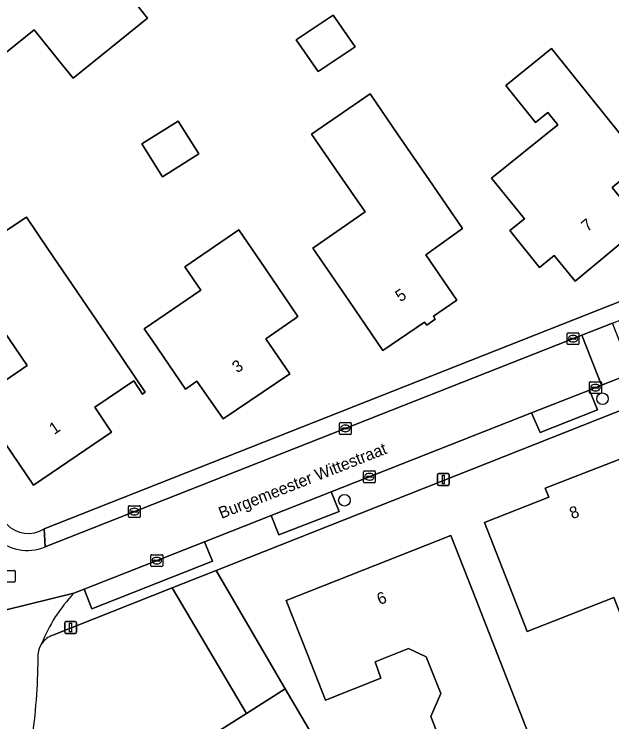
# Model space of a CAD drawing. Extents: x 159499 to 160349, y 382524 to 383273.
# Drawn here: x 159802.6 to 159853.2, y 382906.1 to 382966 of the extents above; entities that cross this region are included whole.
import ezdxf

# ---------------------------------------------------------------- set-up
doc = ezdxf.new("R2010")
doc.units = 0
for name, color, linetype in [('IMGEO_Boom', 7, 'Continuous'), ('IMGEO_Erf', 7, 'Continuous'), ('IMGEO_Groenvoorziening', 7, 'Continuous'), ('IMGEO_Kolk', 7, 'Continuous'), ('IMGEO_Lichtmast', 7, 'Continuous'), ('IMGEO_Openbare_ruimte_label', 7, 'Continuous'), ('IMGEO_Pand', 7, 'Continuous'), ('IMGEO_Pand_nummerreeks', 7, 'Continuous'), ('IMGEO_Parkeervlak_open', 7, 'Continuous'), ('IMGEO_Rijbaan_lokaal_open', 7, 'Continuous'), ('IMGEO_Rioolput', 7, 'Continuous'), ('IMGEO_Voetpad_open', 7, 'Continuous')]:
    doc.layers.add(name, color=color, linetype=linetype)

msp = doc.modelspace()

# ---------------------------------------------------------------- linework, layer by layer
at = {"layer": 'IMGEO_Boom'}
for centre in [(159852.44, 382933.464), (159830.58, 382924.866)]:
    msp.add_circle(centre, 0.489, dxfattribs=at)
at = {"layer": 'IMGEO_Erf'}
for points in [[(159810.687, 382969.677), (159812.684, 382967.19), (159813.906, 382965.668), (159807.597, 382960.604), (159806.377, 382962.124), (159804.314, 382964.694), (159800.336, 382961.498), (159797.462, 382965.076), (159794.331, 382968.974), (159800.665, 382974.051), (159803.594, 382970.401), (159807.555, 382973.575)], [(159829.625, 382965.936), (159831.488, 382963.248), (159828.357, 382961.164), (159826.494, 382963.852)], [(159848.109, 382963.101), (159852.721, 382957.378), (159855.859, 382953.485), (159853.267, 382951.341), (159855.83, 382948.153), (159850.122, 382943.417), (159848.351, 382945.581), (159847.105, 382944.572), (159844.579, 382947.699), (159845.829, 382948.687), (159843.044, 382952.124), (159848.642, 382956.635), (159847.801, 382957.68), (159846.764, 382956.845), (159844.238, 382959.981)], [(159832.762, 382959.268), (159835.116, 382955.835), (159837.748, 382951.997), (159840.576, 382947.873), (159837.474, 382945.651), (159840.098, 382941.809), (159838.121, 382940.456), (159838.275, 382940.209), (159837.549, 382939.692), (159837.359, 382939.953), (159833.819, 382937.55), (159831, 382941.681), (159827.903, 382946.22), (159832.335, 382949.291), (159830.175, 382952.411), (159827.804, 382955.868)], [(159816.49, 382956.966), (159818.245, 382954.196), (159815.182, 382952.255), (159813.426, 382955.025)], [(159807.09, 382943.762), (159810.9, 382938.157), (159813.711, 382934.022), (159813.481, 382933.854), (159812.732, 382934.98), (159809.429, 382932.761), (159810.232, 382931.566), (159810.856, 382930.637), (159804.242, 382926.147), (159799.36, 382933.326), (159803.7, 382936.281), (159799.681, 382942.183), (159797.796, 382944.952), (159803.648, 382948.828), (159805.528, 382946.062)], [(159826.646, 382940.418), (159826.404, 382940.241), (159823.924, 382938.546), (159825.958, 382935.584), (159820.316, 382931.756), (159818.093, 382934.961), (159817.109, 382934.282), (159814.294, 382938.414), (159813.628, 382939.392), (159818.417, 382942.652), (159817.066, 382944.633), (159821.648, 382947.753), (159823.831, 382944.55)], [(159860.258, 382915.772), (159854.598, 382913.555), (159853.389, 382916.644), (159846.046, 382913.769), (159842.432, 382922.996), (159847.888, 382925.132), (159847.59, 382925.89), (159855.15, 382928.82)], [(159846.866, 382903.296), (159840.225, 382900.649), (159837.9, 382906.568), (159838.747, 382908.507), (159837.494, 382911.622), (159836, 382912.309), (159833.186, 382911.18), (159833.664, 382909.806), (159828.984, 382907.938), (159827.481, 382911.745), (159825.644, 382916.395), (159839.605, 382921.884), (159841.424, 382917.227)]]:
    msp.add_lwpolyline(points, close=True, dxfattribs=at)
for points in [[(159805.148, 382922.46), (159871.857, 382948.784)], [(159876.5, 382941.374), (159819.719, 382918.916), (159824.775, 382910.258), (159825.57, 382908.897), (159828.09, 382904.582), (159835.486, 382892.537), (159864.819, 382904.203), (159872.995, 382898.326), (159887.39, 382888.81), (159898.82, 382899.272), (159898.169, 382899.97), (159898.75, 382900.538), (159897.338, 382901.983), (159899.452, 382904.048), (159897.237, 382906.374), (159896.798, 382905.952), (159895.793, 382906.945), (159896.237, 382907.385), (159892.868, 382910.834), (159884.436, 382902.771), (159882.298, 382900.727), (159879.16, 382904.008), (159881.283, 382906.041), (159891.329, 382915.663)]]:
    msp.add_lwpolyline(points, dxfattribs=at)
msp.add_arc((159803.794, 382924.566), 2.504, 222.61592, 302.72825, dxfattribs=at)
at = {"layer": 'IMGEO_Groenvoorziening'}
msp.add_lwpolyline([(159825.57, 382908.897), (159824.775, 382910.258), (159819.719, 382918.916), (159816, 382917.445), (159822.273, 382906.815)], close=True, dxfattribs=at)
for points in [[(159818.914, 382904.693), (159822.273, 382906.815), (159816, 382917.445), (159805.876, 382913.439)], [(159828.09, 382904.582), (159825.57, 382908.897), (159822.273, 382906.815), (159818.914, 382904.693)]]:
    msp.add_lwpolyline(points, dxfattribs=at)
for centre, radius, start, end in [((159806.442, 382911.721), 1.809, 108.23379, 146.35942), ((159806.437, 382911.725), 1.802, 146.3718, 174.39122), ((159750.82, 382912.013), 53.823, 352.42978, 359.88104)]:
    msp.add_arc(centre, radius, start, end, dxfattribs=at)
at = {"layer": 'IMGEO_Kolk'}
for p, q in [((159849.443, 382938.12), (159849.443, 382938.972)), ((159849.518, 382939.046), (159850.37, 382939.046)), ((159850.444, 382938.972), (159850.444, 382938.12)), ((159849.702, 382938.54), (159849.702, 382938.552)), ((159850.14, 382938.503), (159849.742, 382938.503)), ((159849.745, 382938.589), (159850.143, 382938.589)), ((159849.931, 382938.826), (159849.956, 382938.826)), ((159850.186, 382938.552), (159850.186, 382938.54)), ((159850.37, 382938.046), (159849.518, 382938.046)), ((159849.954, 382938.266), (159849.929, 382938.266)), ((159851.337, 382933.975), (159851.337, 382934.827)), ((159851.412, 382934.901), (159852.264, 382934.901)), ((159852.338, 382934.827), (159852.338, 382933.975)), ((159851.596, 382934.395), (159851.596, 382934.407)), ((159852.034, 382934.358), (159851.636, 382934.358)), ((159851.639, 382934.444), (159852.037, 382934.444)), ((159851.825, 382934.681), (159851.85, 382934.681)), ((159852.08, 382934.407), (159852.08, 382934.395)), ((159852.264, 382933.901), (159851.412, 382933.901)), ((159851.848, 382934.121), (159851.823, 382934.121)), ((159830.163, 382930.523), (159830.163, 382931.375)), ((159830.238, 382931.449), (159831.09, 382931.449)), ((159830.651, 382931.229), (159830.676, 382931.229)), ((159831.164, 382931.375), (159831.164, 382930.523)), ((159830.422, 382930.943), (159830.422, 382930.955)), ((159830.86, 382930.906), (159830.462, 382930.906)), ((159830.465, 382930.992), (159830.863, 382930.992)), ((159830.674, 382930.669), (159830.649, 382930.669)), ((159830.906, 382930.955), (159830.906, 382930.943)), ((159831.09, 382930.449), (159830.238, 382930.449)), ((159832.191, 382926.429), (159832.191, 382927.281)), ((159832.266, 382927.355), (159833.118, 382927.355)), ((159832.679, 382927.135), (159832.704, 382927.135)), ((159833.192, 382927.281), (159833.192, 382926.429)), ((159832.45, 382926.849), (159832.45, 382926.861)), ((159832.888, 382926.812), (159832.49, 382926.812)), ((159832.493, 382926.898), (159832.891, 382926.898)), ((159832.702, 382926.575), (159832.677, 382926.575)), ((159832.934, 382926.861), (159832.934, 382926.849)), ((159833.118, 382926.355), (159832.266, 382926.355)), ((159812.291, 382923.481), (159812.291, 382924.333)), ((159812.366, 382924.407), (159813.218, 382924.407)), ((159812.779, 382924.187), (159812.804, 382924.187)), ((159813.292, 382924.333), (159813.292, 382923.481)), ((159813.218, 382923.407), (159812.366, 382923.407)), ((159812.55, 382923.901), (159812.55, 382923.913)), ((159812.988, 382923.864), (159812.59, 382923.864)), ((159812.593, 382923.95), (159812.991, 382923.95)), ((159812.802, 382923.627), (159812.777, 382923.627)), ((159813.034, 382923.913), (159813.034, 382923.901)), ((159814.186, 382919.332), (159814.186, 382920.184)), ((159814.261, 382920.258), (159815.113, 382920.258)), ((159814.674, 382920.038), (159814.699, 382920.038)), ((159815.187, 382920.184), (159815.187, 382919.332)), ((159815.113, 382919.258), (159814.261, 382919.258)), ((159814.445, 382919.752), (159814.445, 382919.764)), ((159814.883, 382919.715), (159814.485, 382919.715)), ((159814.488, 382919.801), (159814.886, 382919.801)), ((159814.697, 382919.478), (159814.672, 382919.478)), ((159814.929, 382919.764), (159814.929, 382919.752))]:
    msp.add_line(p, q, dxfattribs=at)
for points in [[(159849.443, 382938.12), (159849.443, 382938.972)], [(159849.518, 382939.046), (159850.37, 382939.046)], [(159850.444, 382938.972), (159850.444, 382938.12)], [(159850.37, 382938.046), (159849.518, 382938.046)], [(159851.337, 382933.975), (159851.337, 382934.827)], [(159851.412, 382934.901), (159852.264, 382934.901)], [(159852.338, 382934.827), (159852.338, 382933.975)], [(159852.264, 382933.901), (159851.412, 382933.901)], [(159830.163, 382930.523), (159830.163, 382931.375)], [(159830.238, 382931.449), (159831.09, 382931.449)], [(159831.164, 382931.375), (159831.164, 382930.523)], [(159831.09, 382930.449), (159830.238, 382930.449)], [(159832.191, 382926.429), (159832.191, 382927.281)], [(159832.266, 382927.355), (159833.118, 382927.355)], [(159833.192, 382927.281), (159833.192, 382926.429)], [(159833.118, 382926.355), (159832.266, 382926.355)], [(159812.291, 382923.481), (159812.291, 382924.333)], [(159812.366, 382924.407), (159813.218, 382924.407)], [(159813.292, 382924.333), (159813.292, 382923.481)], [(159813.218, 382923.407), (159812.366, 382923.407)], [(159814.186, 382919.332), (159814.186, 382920.184)], [(159814.261, 382920.258), (159815.113, 382920.258)], [(159815.187, 382920.184), (159815.187, 382919.332)], [(159815.113, 382919.258), (159814.261, 382919.258)]]:
    msp.add_lwpolyline(points, dxfattribs=at)
for centre, radius, start, end in [((159849.52, 382938.97), 0.0765, 91.55205, 178.44795), ((159849.52, 382938.97), 0.0765, 91.55205, 178.44795), ((159850.368, 382938.97), 0.0765, 1.55205, 88.44795), ((159850.368, 382938.97), 0.0765, 1.55205, 88.44795), ((159849.742, 382938.549), 0.0403, 85.87752, 175.75265), ((159849.739, 382938.539), 0.0366, 178.93798, 274.71019), ((159850.143, 382938.546), 0.043, 264.86636, 352.45326), ((159850.147, 382938.551), 0.0386, 1.73085, 96.63898), ((159849.52, 382938.122), 0.0765, 181.55205, 268.44795), ((159849.52, 382938.122), 0.0765, 181.55205, 268.44795), ((159850.368, 382938.122), 0.0765, 271.55205, 358.44795), ((159850.368, 382938.122), 0.0765, 271.55205, 358.44795), ((159851.414, 382934.825), 0.0765, 91.55205, 178.44795), ((159851.414, 382934.825), 0.0765, 91.55205, 178.44795), ((159852.262, 382934.825), 0.0765, 1.55205, 88.44795), ((159852.262, 382934.825), 0.0765, 1.55205, 88.44795), ((159851.636, 382934.404), 0.0403, 85.87752, 175.75265), ((159851.633, 382934.394), 0.0366, 178.93798, 274.71019), ((159852.037, 382934.401), 0.043, 264.86636, 352.45326), ((159852.041, 382934.406), 0.0386, 1.73085, 96.63898), ((159851.414, 382933.977), 0.0765, 181.55205, 268.44795), ((159851.414, 382933.977), 0.0765, 181.55205, 268.44795), ((159852.262, 382933.977), 0.0765, 271.55205, 358.44795), ((159852.262, 382933.977), 0.0765, 271.55205, 358.44795), ((159830.24, 382931.373), 0.0765, 91.55205, 178.44795), ((159830.24, 382931.373), 0.0765, 91.55205, 178.44795), ((159831.088, 382931.373), 0.0765, 1.55205, 88.44795), ((159831.088, 382931.373), 0.0765, 1.55205, 88.44795), ((159830.462, 382930.952), 0.0403, 85.87752, 175.75265), ((159830.459, 382930.942), 0.0366, 178.93798, 274.71019), ((159830.863, 382930.949), 0.043, 264.86636, 352.45326), ((159830.867, 382930.954), 0.0386, 1.73085, 96.63898), ((159830.24, 382930.525), 0.0765, 181.55205, 268.44795), ((159830.24, 382930.525), 0.0765, 181.55205, 268.44795), ((159831.088, 382930.525), 0.0765, 271.55205, 358.44795), ((159831.088, 382930.525), 0.0765, 271.55205, 358.44795), ((159832.268, 382927.279), 0.0765, 91.55205, 178.44795), ((159832.268, 382927.279), 0.0765, 91.55205, 178.44795), ((159833.116, 382927.279), 0.0765, 1.55205, 88.44795), ((159833.116, 382927.279), 0.0765, 1.55205, 88.44795), ((159832.268, 382926.431), 0.0765, 181.55205, 268.44795), ((159832.268, 382926.431), 0.0765, 181.55205, 268.44795), ((159832.49, 382926.858), 0.0403, 85.87752, 175.75265), ((159832.487, 382926.848), 0.0366, 178.93798, 274.71019), ((159832.891, 382926.855), 0.043, 264.86636, 352.45326), ((159832.895, 382926.86), 0.0386, 1.73085, 96.63898), ((159833.116, 382926.431), 0.0765, 271.55205, 358.44795), ((159833.116, 382926.431), 0.0765, 271.55205, 358.44795), ((159812.368, 382924.331), 0.0765, 91.55205, 178.44795), ((159812.368, 382924.331), 0.0765, 91.55205, 178.44795), ((159813.216, 382924.331), 0.0765, 1.55205, 88.44795), ((159813.216, 382924.331), 0.0765, 1.55205, 88.44795), ((159812.368, 382923.483), 0.0765, 181.55205, 268.44795), ((159812.368, 382923.483), 0.0765, 181.55205, 268.44795), ((159812.59, 382923.91), 0.0403, 85.87752, 175.75265), ((159812.587, 382923.9), 0.0366, 178.93798, 274.71019), ((159812.991, 382923.907), 0.043, 264.86636, 352.45326), ((159812.995, 382923.912), 0.0386, 1.73085, 96.63898), ((159813.216, 382923.483), 0.0765, 271.55205, 358.44795), ((159813.216, 382923.483), 0.0765, 271.55205, 358.44795), ((159814.263, 382920.182), 0.0765, 91.55205, 178.44795), ((159814.263, 382920.182), 0.0765, 91.55205, 178.44795), ((159815.111, 382920.182), 0.0765, 1.55205, 88.44795), ((159815.111, 382920.182), 0.0765, 1.55205, 88.44795), ((159814.263, 382919.334), 0.0765, 181.55205, 268.44795), ((159814.263, 382919.334), 0.0765, 181.55205, 268.44795), ((159814.485, 382919.761), 0.0403, 85.87752, 175.75265), ((159814.482, 382919.751), 0.0366, 178.93798, 274.71019), ((159814.886, 382919.758), 0.043, 264.86636, 352.45326), ((159814.89, 382919.763), 0.0386, 1.73085, 96.63898), ((159815.111, 382919.334), 0.0765, 271.55205, 358.44795), ((159815.111, 382919.334), 0.0765, 271.55205, 358.44795)]:
    msp.add_arc(centre, radius, start, end, dxfattribs=at)
for centre, major_axis, ratio, start_param, end_param in [((159849.93, 382938.546), (-0.387, 0.002), 0.722429, 4.712389, 7.853982), ((159849.955, 382938.546), (-0.39, 0.002), 0.717154, 1.570796, 4.712389), ((159851.824, 382934.401), (-0.387, 0.002), 0.722429, 4.712389, 7.853982), ((159851.849, 382934.401), (-0.39, 0.002), 0.717154, 1.570796, 4.712389), ((159830.65, 382930.949), (-0.387, 0.002), 0.722429, 4.712389, 7.853982), ((159830.675, 382930.949), (-0.39, 0.002), 0.717154, 1.570796, 4.712389), ((159832.678, 382926.855), (-0.387, 0.002), 0.722429, 4.712389, 7.853982), ((159832.703, 382926.855), (-0.39, 0.002), 0.717154, 1.570796, 4.712389), ((159812.778, 382923.907), (-0.387, 0.002), 0.722429, 4.712389, 7.853982), ((159812.803, 382923.907), (-0.39, 0.002), 0.717154, 1.570796, 4.712389), ((159814.673, 382919.758), (-0.387, 0.002), 0.722429, 4.712389, 7.853982), ((159814.698, 382919.758), (-0.39, 0.002), 0.717154, 1.570796, 4.712389)]:
    msp.add_ellipse(centre, major_axis=major_axis, ratio=ratio, start_param=start_param, end_param=end_param, dxfattribs=at)
at = {"layer": 'IMGEO_Lichtmast'}
for p, q in [((159838.471, 382926.224), (159838.471, 382927.024)), ((159838.471, 382927.024), (159838.471, 382926.224)), ((159838.571, 382927.124), (159839.361, 382927.124)), ((159839.361, 382927.124), (159838.571, 382927.124)), ((159839.461, 382927.024), (159839.461, 382926.224)), ((159839.461, 382926.224), (159839.461, 382927.024)), ((159839.361, 382926.124), (159838.571, 382926.124)), ((159838.571, 382926.124), (159839.361, 382926.124)), ((159806.89, 382913.698), (159806.89, 382914.498)), ((159806.89, 382914.498), (159806.89, 382913.698)), ((159806.99, 382914.598), (159807.78, 382914.598)), ((159807.78, 382914.598), (159806.99, 382914.598)), ((159807.88, 382914.498), (159807.88, 382913.698)), ((159807.88, 382913.698), (159807.88, 382914.498)), ((159807.78, 382913.598), (159806.99, 382913.598)), ((159806.99, 382913.598), (159807.78, 382913.598))]:
    msp.add_line(p, q, dxfattribs=at)
for points in [[(159838.891, 382926.999), (159839.041, 382926.999), (159839.041, 382926.249), (159838.891, 382926.249), (159838.891, 382926.999)], [(159807.31, 382914.473), (159807.46, 382914.473), (159807.46, 382913.723), (159807.31, 382913.723), (159807.31, 382914.473)]]:
    msp.add_lwpolyline(points, dxfattribs=at)
for centre, start, end in [((159838.571, 382927.024), 90, 180), ((159838.571, 382927.024), 90, 180), ((159839.361, 382927.024), 0, 90), ((159839.361, 382927.024), 360, 90), ((159838.571, 382926.224), 180, 270), ((159838.571, 382926.224), 180, 270), ((159839.361, 382926.224), 270, 0), ((159839.361, 382926.224), 270, 0), ((159806.99, 382914.498), 90, 180), ((159806.99, 382914.498), 90, 180), ((159807.78, 382914.498), 0, 90), ((159807.78, 382914.498), 360, 90), ((159806.99, 382913.698), 180, 270), ((159806.99, 382913.698), 180, 270), ((159807.78, 382913.698), 270, 0), ((159807.78, 382913.698), 270, 0)]:
    msp.add_arc(centre, 0.1, start, end, dxfattribs=at)
at = {"layer": 'IMGEO_Pand'}
for points in [[(159810.687, 382969.677), (159807.555, 382973.575), (159803.594, 382970.401), (159800.665, 382974.051), (159794.331, 382968.974), (159797.462, 382965.076), (159800.336, 382961.498), (159804.314, 382964.694), (159806.377, 382962.124), (159807.597, 382960.604), (159813.906, 382965.668), (159812.684, 382967.19)], [(159828.357, 382961.164), (159831.488, 382963.248), (159829.625, 382965.936), (159826.494, 382963.852)], [(159852.721, 382957.378), (159848.109, 382963.101), (159844.238, 382959.981), (159846.764, 382956.845), (159847.801, 382957.68), (159848.642, 382956.635), (159843.044, 382952.124), (159845.829, 382948.687), (159844.579, 382947.699), (159847.105, 382944.572), (159848.351, 382945.581), (159850.122, 382943.417), (159855.83, 382948.153), (159853.267, 382951.341), (159855.859, 382953.485)], [(159835.116, 382955.835), (159832.762, 382959.268), (159827.804, 382955.868), (159830.175, 382952.411), (159832.335, 382949.291), (159827.903, 382946.22), (159831, 382941.681), (159833.819, 382937.55), (159837.359, 382939.953), (159837.549, 382939.692), (159838.275, 382940.209), (159838.121, 382940.456), (159840.098, 382941.809), (159837.474, 382945.651), (159840.576, 382947.873), (159837.748, 382951.997)], [(159815.182, 382952.255), (159818.245, 382954.196), (159816.49, 382956.966), (159813.426, 382955.025)], [(159807.09, 382943.762), (159805.528, 382946.062), (159803.648, 382948.828), (159797.796, 382944.952), (159799.681, 382942.183), (159803.7, 382936.281), (159799.36, 382933.326), (159804.242, 382926.147), (159810.856, 382930.637), (159810.232, 382931.566), (159809.429, 382932.761), (159812.732, 382934.98), (159813.481, 382933.854), (159813.711, 382934.022), (159810.9, 382938.157)], [(159826.404, 382940.241), (159826.646, 382940.418), (159823.831, 382944.55), (159821.648, 382947.753), (159817.066, 382944.633), (159818.417, 382942.652), (159813.628, 382939.392), (159814.294, 382938.414), (159817.109, 382934.282), (159818.093, 382934.961), (159820.316, 382931.756), (159825.958, 382935.584), (159823.924, 382938.546)], [(159854.598, 382913.555), (159860.258, 382915.772), (159855.15, 382928.82), (159847.59, 382925.89), (159847.888, 382925.132), (159842.432, 382922.996), (159846.046, 382913.769), (159853.389, 382916.644)], [(159833.664, 382909.806), (159833.186, 382911.18), (159836, 382912.309), (159837.494, 382911.622), (159838.747, 382908.507), (159837.9, 382906.568), (159840.225, 382900.649), (159846.866, 382903.296), (159841.424, 382917.227), (159839.605, 382921.884), (159825.644, 382916.395), (159827.481, 382911.745), (159828.984, 382907.938)]]:
    msp.add_lwpolyline(points, close=True, dxfattribs=at)
at = {"layer": 'IMGEO_Parkeervlak_open'}
for points in [[(159851.334, 382934.196), (159846.419, 382932.259), (159847.155, 382930.599), (159852.001, 382932.516)], [(159824.384, 382923.582), (159825.032, 382921.94), (159830.133, 382923.927), (159829.466, 382925.58)], [(159808.536, 382917.335), (159809.177, 382915.674), (159819.408, 382919.703), (159818.738, 382921.356)]]:
    msp.add_lwpolyline(points, close=True, dxfattribs=at)
at = {"layer": 'IMGEO_Rijbaan_lokaal_open'}
for points in [[(159871.857, 382948.784), (159805.148, 382922.46), (159805.224, 382920.924), (159850.691, 382938.839)], [(159850.691, 382938.839), (159853.277, 382939.858), (159872.506, 382947.434)], [(159818.738, 382921.356), (159824.384, 382923.582), (159829.466, 382925.58), (159846.419, 382932.259), (159851.334, 382934.196), (159852.36, 382934.6), (159850.691, 382938.839), (159805.224, 382920.924)], [(159805.224, 382920.924), (159805.148, 382922.46)], [(159798.017, 382914.622), (159807.664, 382916.991), (159808.536, 382917.335), (159818.738, 382921.356)], [(159807.664, 382916.991), (159798.017, 382914.622)]]:
    msp.add_lwpolyline(points, dxfattribs=at)
msp.add_lwpolyline([(159854.946, 382935.619), (159853.277, 382939.858), (159850.691, 382938.839), (159852.36, 382934.6)], close=True, dxfattribs=at)
for centre, radius, start, end in [((159803.794, 382924.566), 2.504, 222.61592, 302.72825), ((159803.714, 382924.467), 3.851, 224.68021, 293.07887), ((159803.714, 382924.467), 3.851, 224.68021, 293.07887), ((159817.242, 382907.863), 13.231, 136.37871, 158.44988), ((159806.437, 382911.725), 1.802, 146.3718, 174.39122), ((159750.82, 382912.013), 53.823, 352.42978, 359.88104)]:
    msp.add_arc(centre, radius, start, end, dxfattribs=at)
at = {"layer": 'IMGEO_Rioolput'}
for p, q in [((159801.756, 382918.935), (159802.608, 382918.935)), ((159802.682, 382918.861), (159802.682, 382918.009)), ((159802.608, 382917.935), (159801.756, 382917.935))]:
    msp.add_line(p, q, dxfattribs=at)
for points in [[(159801.756, 382918.935), (159802.608, 382918.935)], [(159802.682, 382918.861), (159802.682, 382918.009)], [(159802.608, 382917.935), (159801.756, 382917.935)]]:
    msp.add_lwpolyline(points, dxfattribs=at)
for centre, start, end in [((159802.606, 382918.859), 1.55205, 88.44795), ((159802.606, 382918.859), 1.55205, 88.44795), ((159802.606, 382918.011), 271.55205, 358.44795), ((159802.606, 382918.011), 271.55205, 358.44795)]:
    msp.add_arc(centre, 0.0765, start, end, dxfattribs=at)
at = {"layer": 'IMGEO_Voetpad_open'}
for points in [[(159872.735, 382942.627), (159868.238, 382940.855), (159868.916, 382939.194), (159863.994, 382937.243), (159863.33, 382938.922), (159854.946, 382935.619), (159852.36, 382934.6), (159851.334, 382934.196), (159852.001, 382932.516), (159847.155, 382930.599), (159846.419, 382932.259), (159829.466, 382925.58), (159830.133, 382923.927), (159825.032, 382921.94), (159824.384, 382923.582), (159818.738, 382921.356), (159819.408, 382919.703), (159809.177, 382915.674), (159808.536, 382917.335), (159807.664, 382916.991)], [(159805.876, 382913.439), (159816, 382917.445), (159819.719, 382918.916), (159876.5, 382941.374)]]:
    msp.add_lwpolyline(points, dxfattribs=at)
for centre, radius, start, end in [((159817.242, 382907.863), 13.231, 136.37871, 158.44988), ((159806.442, 382911.721), 1.809, 108.23379, 146.35942)]:
    msp.add_arc(centre, radius, start, end, dxfattribs=at)

# ---------------------------------------------------------------- texts
at = {"layer": 'IMGEO_Openbare_ruimte_label'}
msp.add_text('Burgemeester Wittestraat', height=1, rotation=21.53536, dxfattribs=at).set_placement((159820.16, 382923.281))
at = {"layer": 'IMGEO_Pand_nummerreeks'}
for s, rotation, p in [('7', 39.68292, (159851.155, 382947.549)), ('5', 34.14876, (159835.316, 382941.61)), ('3', 34.15401, (159821.494, 382935.601)), ('1', 34.1712, (159806, 382930.386)), ('8', 21.18464, (159849.872, 382923.256)), ('6', 21.46309, (159833.568, 382915.987))]:
    msp.add_text(s, height=1, rotation=rotation, dxfattribs=at).set_placement(p)

doc.saveas('drawing.dxf')
